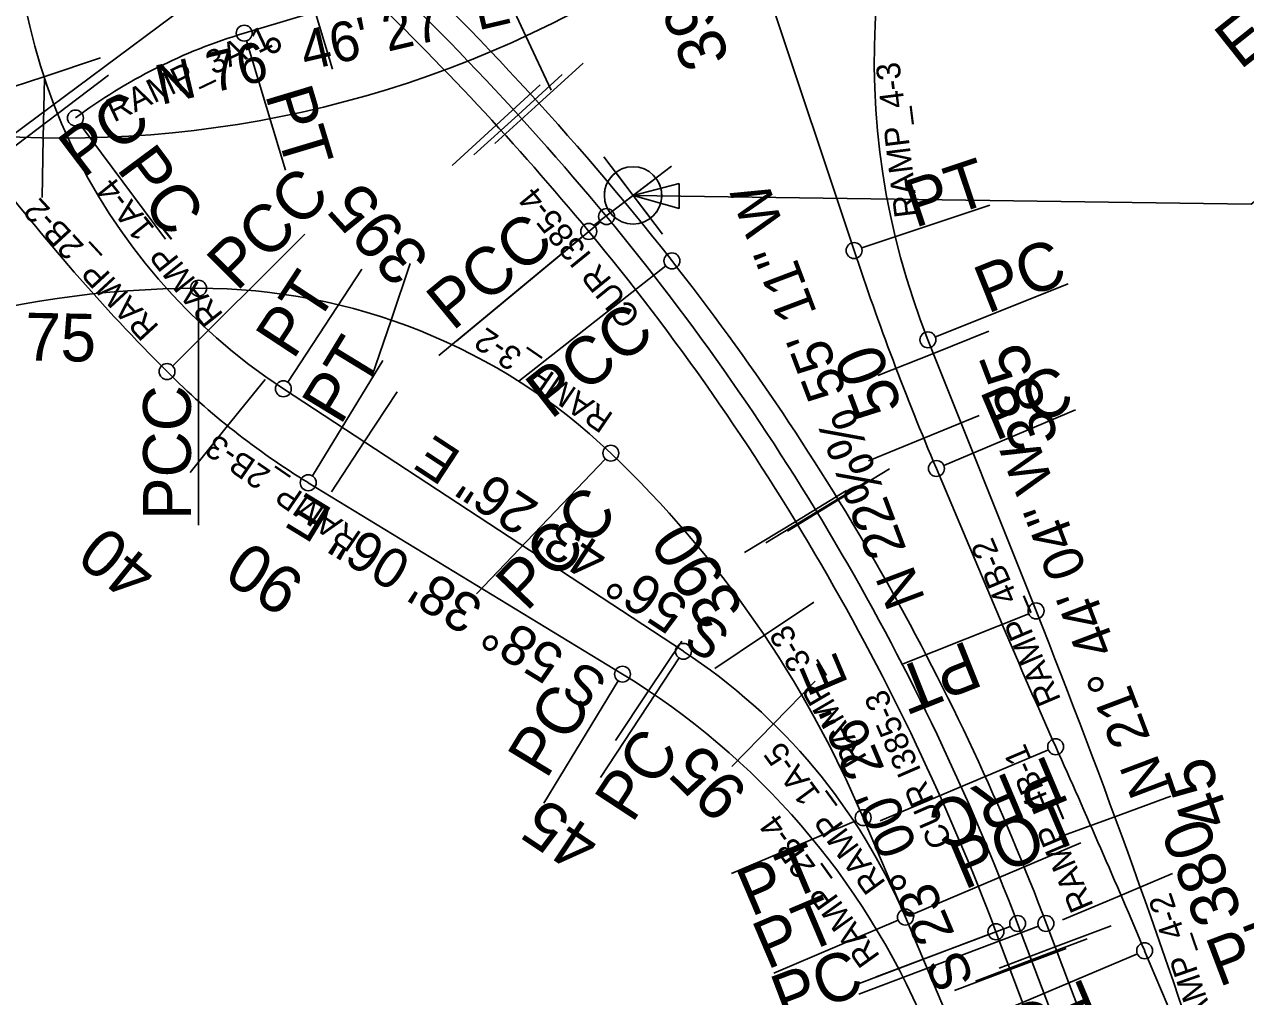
# Model space of a CAD drawing. Extents: x 1603447 to 1622636, y 1083818 to 1103958.
# Drawn here: x 1610566 to 1611793, y 1092741 to 1093718 of the extents above; entities that cross this region are included whole.
import ezdxf

# ---------------------------------------------------------------- set-up
doc = ezdxf.new("R2010")
doc.units = 0
for name, color, linetype in [('Level 1', 7, 'Continuous'), ('RD_HC_Points', 7, 'Continuous'), ('RD_HC_SUR_Bearing_TX400', 7, 'Continuous'), ('RD_HC_SUR_CL400', 7, 'Continuous'), ('RD_HC_SUR_PC_PT_400', 7, 'Continuous'), ('RD_HC_SUR_Tic400', 7, 'Continuous'), ('RD_HC_SUR_TX_Sta400', 7, 'Continuous'), ('RD_SHT_Misc1', 7, 'Continuous'), ('RD_TX_Misc1', 7, 'Continuous')]:
    doc.layers.add(name, color=color, linetype=linetype)

msp = doc.modelspace()

# ---------------------------------------------------------------- linework, layer by layer
at = {"layer": 'RD_HC_Points'}
msp.add_lwpolyline([(1611865.6, 1093590.8), (1611798.8, 1093537.7), (1611177.7, 1093546.4)], dxfattribs=at)
msp.add_lwpolyline([(1611224.2, 1093558.2), (1611177.7, 1093546.4), (1611223.9, 1093533.3)], close=True, dxfattribs=at)
at = {"layer": 'RD_HC_SUR_CL400'}
for p, q in [((1609780.9, 1093032.2), (1610899.7, 1093863.9)), ((1611399.8, 1093491), (1611279.1, 1093852.8)), ((1610787.1, 1093709.4), (1611124.6, 1093811)), ((1611582.6, 1093128.9), (1611474, 1093401.3)), ((1610826.4, 1093352.1), (1611228.3, 1093088.3)), ((1611548.7, 1093115.4), (1611482.5, 1093272)), ((1610851.4, 1093257.7), (1611167.1, 1093065.3)), ((1611408.9, 1092921.1), (1611451.4, 1092821.2)), ((1611451.4, 1092821.2), (1611594.4, 1092484.4)), ((1612051.1, 1091527.2), (1611564.1, 1092814.8)), ((1612071.1, 1091550.5), (1611593.4, 1092813.6)), ((1611906.2, 1091844.6), (1611542.3, 1092806.5)), ((1611720.1, 1092720.3), (1611691.7, 1092787.4))]:
    msp.add_line(p, q, dxfattribs=at)
for centre, radius, start, end in [((1611155.6, 1093853.7), 600, 109.8521, 236.724), ((1608910.9, 1091669.6), 2932.1, 37.9336, 56.1301), ((1608910.9, 1091669.6), 2908.8, 39.6334, 56.1301), ((1612180, 1093682.7), 760, 149.6819, 201.7343), ((1608910.9, 1091669.6), 2885.6, 39.6334, 53.0731), ((1610606.4, 1094704), 1100, 229.4294, 303.6278), ((1610945.6, 1093182.8), 550, 106.7519, 126.6256), ((1612124, 1094783.4), 2000, 217.1508, 224.9911), ((1609225.7, 1091930.4), 2500, 20.7167, 39.6334), ((1609225.7, 1091930.4), 2476.8, 20.7167, 39.6334), ((1614245.6, 1094440.3), 3000, 198.4471, 202.9196), ((1609233.5, 1091921.1), 2523, 20.7167, 37.9336), ((1610741.6, 1092453.1), 1000, 90.0249, 122.6256), ((1610741.4, 1092853.1), 600, 46.3737, 90.0249), ((1611247, 1093906.7), 760, 224.9911, 238.635), ((1610396.4, 1092491.2), 1100, 23.0073, 46.3737), ((1604151.3, 1090166.4), 8000, 17.77323, 21.73435), ((1617075, 1095452), 6000, 202.91963, 204.20083), ((1610899.1, 1092586.6), 600, 23.0073, 56.724), ((1610771.5, 1092416.4), 760, 23.0073, 58.635), ((1602481.2, 1088893), 10000, 22.91963, 24.20083)]:
    msp.add_arc(centre, radius, start, end, dxfattribs=at)
at = {"layer": 'RD_HC_SUR_PC_PT_400'}
for p, q in [((1610789.4, 1093701.8), (1610828.5, 1093571.7)), ((1610536.2, 1093580.4), (1610650.8, 1093667.2)), ((1610622.3, 1093617.7), (1610708, 1093502.4)), ((1611407.4, 1093493.6), (1611536.2, 1093536.6)), ((1611144.9, 1093520), (1611000.6, 1093400.4)), ((1610715.2, 1093375), (1610847.8, 1093507.6)), ((1611127, 1093505.1), (1610982.6, 1093385.6)), ((1611210.5, 1093475.7), (1611063.1, 1093359.9)), ((1610830.8, 1093358.7), (1610905.3, 1093472.3)), ((1611481.5, 1093404.2), (1611615, 1093457.5)), ((1610741.2, 1093445.1), (1610741.3, 1093215.2)), ((1610855.6, 1093264.6), (1610926.3, 1093380.6)), ((1611489.9, 1093275.1), (1611622.3, 1093331.1)), ((1611149.9, 1093281.6), (1611020.5, 1093145.9)), ((1611575.2, 1093125.9), (1611449, 1093075.6)), ((1611223.9, 1093081.6), (1611145, 1092961.4)), ((1611162.9, 1093058.5), (1611088.1, 1092935.8)), ((1611595, 1092989.3), (1611426.1, 1092917.8)), ((1611401.6, 1092918), (1611276.5, 1092864.9)), ((1611458.7, 1092824.3), (1611627.6, 1092896)), ((1611458.7, 1092824.3), (1611627.6, 1092896)), ((1611444, 1092818), (1611319, 1092764.9)), ((1611585, 1092812), (1611404.6, 1092743.7)), ((1611556.6, 1092811.9), (1611422.1, 1092761.1)), ((1611534.9, 1092803.7), (1611400.4, 1092752.8)), ((1611684.4, 1092784.3), (1611515.4, 1092712.9))]:
    msp.add_line(p, q, dxfattribs=at)
for centre in [(1610787.1, 1093709.4), (1610617.5, 1093624.2), (1611151.1, 1093525.1), (1611133.2, 1093510.2), (1611399.8, 1093491), (1611216.8, 1093480.6), (1610741.2, 1093453.1), (1611474, 1093401.3), (1610709.5, 1093369.4), (1610826.4, 1093352.1), (1611155.4, 1093287.4), (1611482.5, 1093272), (1610851.4, 1093257.7), (1611582.6, 1093128.9), (1611228.3, 1093088.3), (1611167.1, 1093065.3), (1611602.3, 1092992.4), (1611408.9, 1092921.1), (1611451.4, 1092821.2), (1611451.4, 1092821.2), (1611451.4, 1092821.2), (1611451.4, 1092821.2), (1611542.3, 1092806.5), (1611564.1, 1092814.8), (1611592.5, 1092814.8), (1611691.7, 1092787.4)]:
    msp.add_circle(centre, 8, dxfattribs=at)
at = {"layer": 'RD_HC_SUR_Tic400'}
for p, q in [((1611070.1, 1093706.5), (1611044.8, 1093760.9)), ((1610858.3, 1093730.8), (1610875.6, 1093673.4)), ((1611014.8, 1093711.8), (1611014.8, 1093711.8)), ((1611070.1, 1093706.5), (1611095.4, 1093652.1)), ((1610762.7, 1093701.5), (1610762.7, 1093701.5)), ((1610993.7, 1093700.2), (1610993.7, 1093700.2)), ((1610585.8, 1093665.7), (1610642.8, 1093684.5)), ((1610663, 1093687.9), (1610663, 1093687.9)), ((1610971.5, 1093689.7), (1610971.5, 1093689.7)), ((1611083.2, 1093638.9), (1611127.7, 1093679.2)), ((1611336.9, 1093679.5), (1611336.9, 1093679.5)), ((1611420, 1093679.8), (1611420, 1093679.8)), ((1610585.8, 1093665.7), (1610528.8, 1093646.9)), ((1610585.1, 1093604.2), (1610586.3, 1093664.2)), ((1610671.9, 1093659.8), (1610671.9, 1093659.8)), ((1610681.2, 1093664), (1610681.2, 1093664)), ((1610977.7, 1093668.5), (1610977.7, 1093668.5)), ((1611040.2, 1093617), (1611084.5, 1093657.5)), ((1611062.2, 1093627.4), (1611106.6, 1093667.8)), ((1610882.1, 1093639.1), (1610882.1, 1093639.1)), ((1611083.2, 1093638.9), (1611038.8, 1093598.6)), ((1610582.7, 1093628.2), (1610582.7, 1093628.2)), ((1611062.2, 1093627.4), (1611017.9, 1093587)), ((1610592.8, 1093617.3), (1610592.8, 1093617.3)), ((1610784.3, 1093618.5), (1610784.3, 1093618.5)), ((1611040.2, 1093617), (1610995.9, 1093576.6)), ((1610585.1, 1093604.2), (1610584, 1093544.2)), ((1610685, 1093606.8), (1610685, 1093606.8)), ((1611368.6, 1093584.6), (1611368.6, 1093584.6)), ((1610624.9, 1093573.7), (1610624.9, 1093573.7)), ((1611427, 1093580.1), (1611427, 1093580.1)), ((1611149.1, 1093563.7), (1611149.1, 1093563.7)), ((1611128.3, 1093552.3), (1611128.3, 1093552.3)), ((1611106.4, 1093542.1), (1611106.4, 1093542.1)), ((1610678.7, 1093489.6), (1610678.7, 1093489.6)), ((1611212.4, 1093486.2), (1611212.4, 1093486.2)), ((1611400.2, 1093489.8), (1611400.2, 1093489.8)), ((1610934.6, 1093421.1), (1610953.9, 1093477.9)), ((1611191.6, 1093474.9), (1611191.6, 1093474.9)), ((1611447, 1093482.2), (1611447, 1093482.2)), ((1611169.9, 1093464.8), (1611169.9, 1093464.8)), ((1610628.5, 1093455.3), (1610628.5, 1093455.3)), ((1610738.1, 1093453.1), (1610738.1, 1093453.1)), ((1610638.3, 1093447.7), (1610638.3, 1093447.7)), ((1610837.7, 1093445.3), (1610837.7, 1093445.3)), ((1610745.7, 1093415.5), (1610745.7, 1093415.5)), ((1610934.6, 1093421.1), (1610915.3, 1093364.3)), ((1611272.8, 1093406.6), (1611272.8, 1093406.6)), ((1611479.5, 1093387.7), (1611535.2, 1093409.9)), ((1611251.8, 1093395.1), (1611251.8, 1093395.1)), ((1611479.5, 1093387.7), (1611423.7, 1093365.5)), ((1611433.5, 1093395.5), (1611433.5, 1093395.5)), ((1610696.8, 1093382.2), (1610696.8, 1093382.2)), ((1611026.2, 1093381.2), (1611026.2, 1093381.2)), ((1611230.3, 1093385.1), (1611230.3, 1093385.1)), ((1610770.4, 1093314.7), (1610808, 1093361.4)), ((1610824, 1093353.6), (1610824, 1093353.6)), ((1610907.6, 1093298.7), (1610940.6, 1093348.9)), ((1611109.8, 1093326.7), (1611109.8, 1093326.7)), ((1610770.4, 1093314.7), (1610732.8, 1093268)), ((1611330.1, 1093324.6), (1611330.1, 1093324.6)), ((1611469.9, 1093302.3), (1611525.4, 1093325.1)), ((1611287.3, 1093303), (1611287.3, 1093303)), ((1611308.7, 1093312.9), (1611308.7, 1093312.9)), ((1611469.9, 1093302.3), (1611414.3, 1093279.6)), ((1610907.6, 1093298.7), (1610874.7, 1093248.5)), ((1611516.5, 1093294.8), (1611516.5, 1093294.8)), ((1611384.1, 1093240.4), (1611435.2, 1093271.8)), ((1610852.2, 1093257.3), (1610852.2, 1093257.3)), ((1611183.7, 1093259.4), (1611183.7, 1093259.4)), ((1611362.3, 1093228.5), (1611413.6, 1093259.6)), ((1610991.2, 1093243.8), (1610991.2, 1093243.8)), ((1611384.1, 1093240.4), (1611332.9, 1093209.1)), ((1611341.1, 1093218.7), (1611392.3, 1093249.9)), ((1611362.3, 1093228.5), (1611311.1, 1093197.3)), ((1611341.1, 1093218.7), (1611289.8, 1093187.5)), ((1610937.6, 1093205.2), (1610937.6, 1093205.2)), ((1611508.6, 1093210.2), (1611508.6, 1093210.2)), ((1611553.5, 1093201.9), (1611553.5, 1093201.9)), ((1611074.8, 1093189), (1611074.8, 1093189)), ((1611250.2, 1093184.7), (1611250.2, 1093184.7)), ((1611023, 1093153.2), (1611023, 1093153.2)), ((1611434.7, 1093154.2), (1611434.7, 1093154.2)), ((1611158.5, 1093134.1), (1611158.5, 1093134.1)), ((1611309.7, 1093104.4), (1611359.5, 1093137.8)), ((1611391.3, 1093132.3), (1611391.3, 1093132.3)), ((1611412.5, 1093142), (1611412.5, 1093142)), ((1611547.6, 1093118.1), (1611547.6, 1093118.1)), ((1611590.5, 1093109), (1611590.5, 1093109)), ((1611108.4, 1093101.1), (1611108.4, 1093101.1)), ((1611193.4, 1093048.5), (1611226.7, 1093098.4)), ((1611309.7, 1093104.4), (1611259.8, 1093070.9)), ((1611241.9, 1093079.1), (1611241.9, 1093079.1)), ((1611318.9, 1093015.4), (1611360.8, 1093058.2)), ((1611481.8, 1093066), (1611481.8, 1093066)), ((1611193.4, 1093048.5), (1611160.1, 1092998.6)), ((1611459.2, 1093053.6), (1611459.2, 1093053.6)), ((1611438.1, 1093043.9), (1611438.1, 1093043.9)), ((1611586.5, 1093026), (1611586.5, 1093026)), ((1611318.9, 1093015.4), (1611276.9, 1092972.5)), ((1611361.6, 1093018.9), (1611361.6, 1093018.9)), ((1611626.7, 1093015.8), (1611626.7, 1093015.8)), ((1611272.7, 1092987.7), (1611272.7, 1092987.7)), ((1611525.4, 1092976), (1611525.4, 1092976)), ((1611502.4, 1092963.4), (1611502.4, 1092963.4)), ((1611481.2, 1092953.7), (1611481.2, 1092953.7)), ((1611384.2, 1092939.8), (1611384.2, 1092939.8)), ((1611625.5, 1092933.9), (1611625.5, 1092933.9)), ((1611661.8, 1092922.1), (1611718.1, 1092942.8)), ((1611405.5, 1092929.1), (1611405.5, 1092929.1)), ((1611661.8, 1092922.1), (1611605.4, 1092901.4)), ((1611343.3, 1092917), (1611343.3, 1092917)), ((1611565.4, 1092884.4), (1611565.4, 1092884.4)), ((1611520.7, 1092861.8), (1611520.7, 1092861.8)), ((1611541.8, 1092871.5), (1611541.8, 1092871.5)), ((1611664.4, 1092841.7), (1611719.7, 1092865.1)), ((1611436, 1092854.4), (1611436, 1092854.4)), ((1611404, 1092837.7), (1611404, 1092837.7)), ((1611444.6, 1092837.1), (1611444.6, 1092837.1)), ((1611664.4, 1092841.7), (1611609.1, 1092818.4)), ((1611695.6, 1092828), (1611695.6, 1092828)), ((1611601.8, 1092791.3), (1611658, 1092812.5)), ((1611577.9, 1092778.2), (1611634, 1092799.4)), ((1611601.8, 1092791.3), (1611545.7, 1092770)), ((1611556.7, 1092768.5), (1611612.9, 1092789.7)), ((1611577.9, 1092778.2), (1611521.8, 1092757)), ((1611556.7, 1092768.5), (1611500.6, 1092747.3)), ((1611453.9, 1092751), (1611453.9, 1092751)), ((1611703.4, 1092749.6), (1611703.4, 1092749.6))]:
    msp.add_line(p, q, dxfattribs=at)
at = {"layer": 'RD_SHT_Misc1'}
for p, q in [((1611148.2, 1093585.2), (1611207.2, 1093507.6)), ((1611138.9, 1093516.9), (1611216.5, 1093575.9)), ((1611177.7, 1093546.4), (1611160.3, 1093569.3)), ((1611200.6, 1093563.8), (1611177.7, 1093546.4)), ((1611154.8, 1093529), (1611177.7, 1093546.4)), ((1611177.7, 1093546.4), (1611195.1, 1093523.5))]:
    msp.add_line(p, q, dxfattribs=at)
msp.add_circle((1611177.7, 1093546.4), 28.8, dxfattribs=at)
for start, end in [(127.2464, 217.2464), (307.2464, 37.2464)]:
    msp.add_arc((1611177.7, 1093546.4), 28.8, start, end, dxfattribs=at)

# ---------------------------------------------------------------- texts
at = {"layer": 'Level 1'}
for s, rotation, p in [('395', 132.303, (1610975.3, 1093483.8)), ('75', 358.8916, (1610566.5, 1093380.6)), ('385', 110.7167, (1611606.6, 1093301.7)), ('95', 135.6045, (1611295.4, 1092948.2)), ('45', 109.0877, (1611778.7, 1092918.2)), ('45', 146.2795, (1611147.6, 1092902.8))]:
    msp.add_text(s, height=48, rotation=rotation, dxfattribs=at).set_placement(p)
at = {"layer": 'RD_HC_Points'}
msp.add_text('EL = 992.75', height=48, rotation=38.4995, dxfattribs=at).set_placement((1611787.7, 1093671.9))
at = {"layer": 'RD_HC_SUR_Bearing_TX400'}
for s, rotation, p in [('N 76%%d 46\' 27" E', 13.2258, (1610703.5, 1093637.2)), ('N 22%% 55\' 11" W', 110.7167, (1611471.6, 1093140.7)), ('S 56%%d 43\' 26" E', 146.724, (1611277.9, 1093109.3)), ('N 21%%d 44\' 04" W', 110.7167, (1611716.7, 1092950.9)), ('S 58%%d 38\' 06" E', 148.635, (1611154.3, 1093061.5)), ('S 23%%d 00\' 26" E', 113.0073, (1611521.1, 1092757.6))]:
    msp.add_text(s, height=40, rotation=rotation, dxfattribs=at).set_placement(p)
at = {"layer": 'RD_HC_SUR_PC_PT_400'}
for s, rotation, p in [('PC', 37.1508, (1610624.9, 1093562.7)), ('PT', 286.7519, (1610807.7, 1093647.8)), ('PC', 306.6256, (1610657.9, 1093573.2)), ('PT', 18.4471, (1611460.8, 1093513.5)), ('PCC', 44.9911, (1610779.7, 1093449)), ('PCC', 39.6334, (1610996.4, 1093409.4)), ('PC', 21.7343, (1611533.7, 1093427.2)), ('PT', 56.724, (1610836.2, 1093380.2)), ('PCC', 38.1453, (1611095.1, 1093320.5)), ('PT', 58.635, (1610883.6, 1093314.3)), ('PC', 22.9196, (1611541.6, 1093299.2)), ('PCC', 90.0249, (1610733.5, 1093220.2)), ('PCC', 46.3737, (1611070.6, 1093127.2)), ('PT', 201.7343, (1611513.5, 1093099.5)), ('PC', 58.635, (1611090.5, 1092958.8)), ('PC', 56.724, (1611176.8, 1092914.5)), ('PRC', 202.9196, (1611595.4, 1092984.3)), ('POT', 23.0073, (1611510.4, 1092848.4)), ('POT', 23.0073, (1611510.4, 1092848.4)), ('PT', 23.0073, (1611296.2, 1092821.2)), ('PT', 23.0073, (1611312.3, 1092768.1)), ('PT', 20.7167, (1611766.1, 1092750.7)), ('PC', 20.7167, (1611328.8, 1092714.5)), ('PC', 202.9196, (1611632.6, 1092760.2))]:
    msp.add_text(s, height=48, rotation=rotation, dxfattribs=at).set_placement(p)
at = {"layer": 'RD_HC_SUR_TX_Sta400'}
for s, rotation, p in [('390', 110.7167, (1611275.5, 1093684.1)), ('50', 110.7167, (1611448.9, 1093333.6)), ('40', 141.1632, (1610702.4, 1093171.7)), ('390', 121.2804, (1611290.4, 1093131.1)), ('90', 146.724, (1610850.6, 1093161.7)), ('380', 110.7167, (1611790.4, 1092824.2))]:
    msp.add_text(s, height=48, rotation=rotation, dxfattribs=at).set_placement(p)
at = {"layer": 'RD_TX_Misc1'}
for s, rotation, p in [('RAMP_3A-1', 25.5167, (1610656.1, 1093619.5)), ('RAMP_4-3', 97.0853, (1611464.5, 1093525.6)), ('RAMP_1A-4', 128.4976, (1610766.9, 1093426.5)), ('CUR I385-4', 129.0719, (1611186.4, 1093425.4)), ('RAMP_2B-2', 132.7711, (1610702.3, 1093414.5)), ('RAMP_3-2', 145.6505, (1611159.2, 1093326.2)), ('RAMP_2B-3', 145.5838, (1610906.2, 1093206.6)), ('RAMP_4B-2', 112.9196, (1611608, 1093039.7)), ('RAMP_3-3', 120.308, (1611413.4, 1092981.4)), ('CUR I385-3', 113.5316, (1611498.9, 1092896.3)), ('RAMP_1A-5', 126.2746, (1611432.3, 1092855.5)), ('RAMP_4B-1', 112.943, (1611640.7, 1092832.5)), ('RAMP_2B-4', 125.6188, (1611426.5, 1092781.8)), ('RAMP_4-2', 108.9307, (1611768.7, 1092698.7))]:
    msp.add_text(s, height=24, rotation=rotation, dxfattribs=at).set_placement(p)

doc.saveas('drawing.dxf')
